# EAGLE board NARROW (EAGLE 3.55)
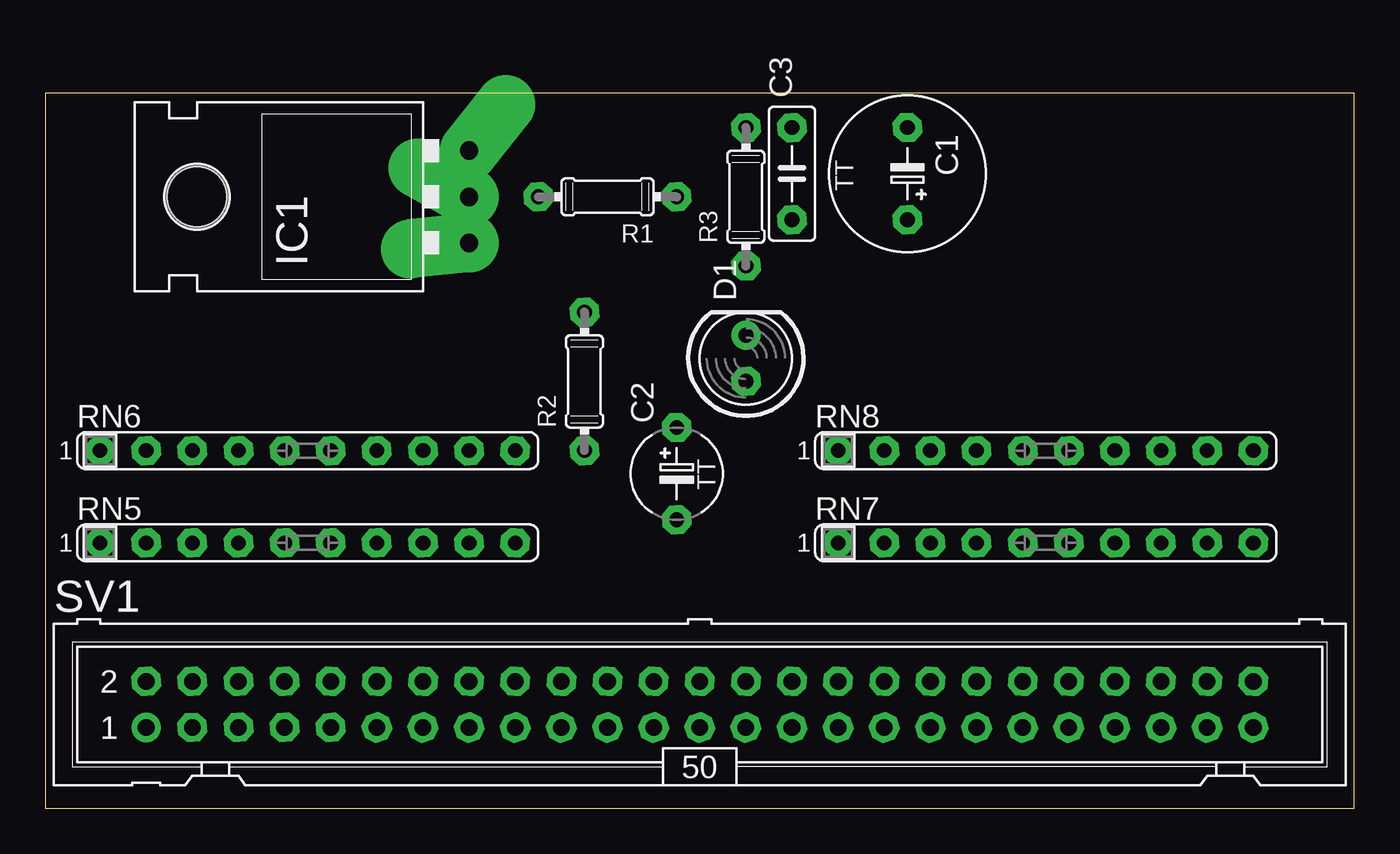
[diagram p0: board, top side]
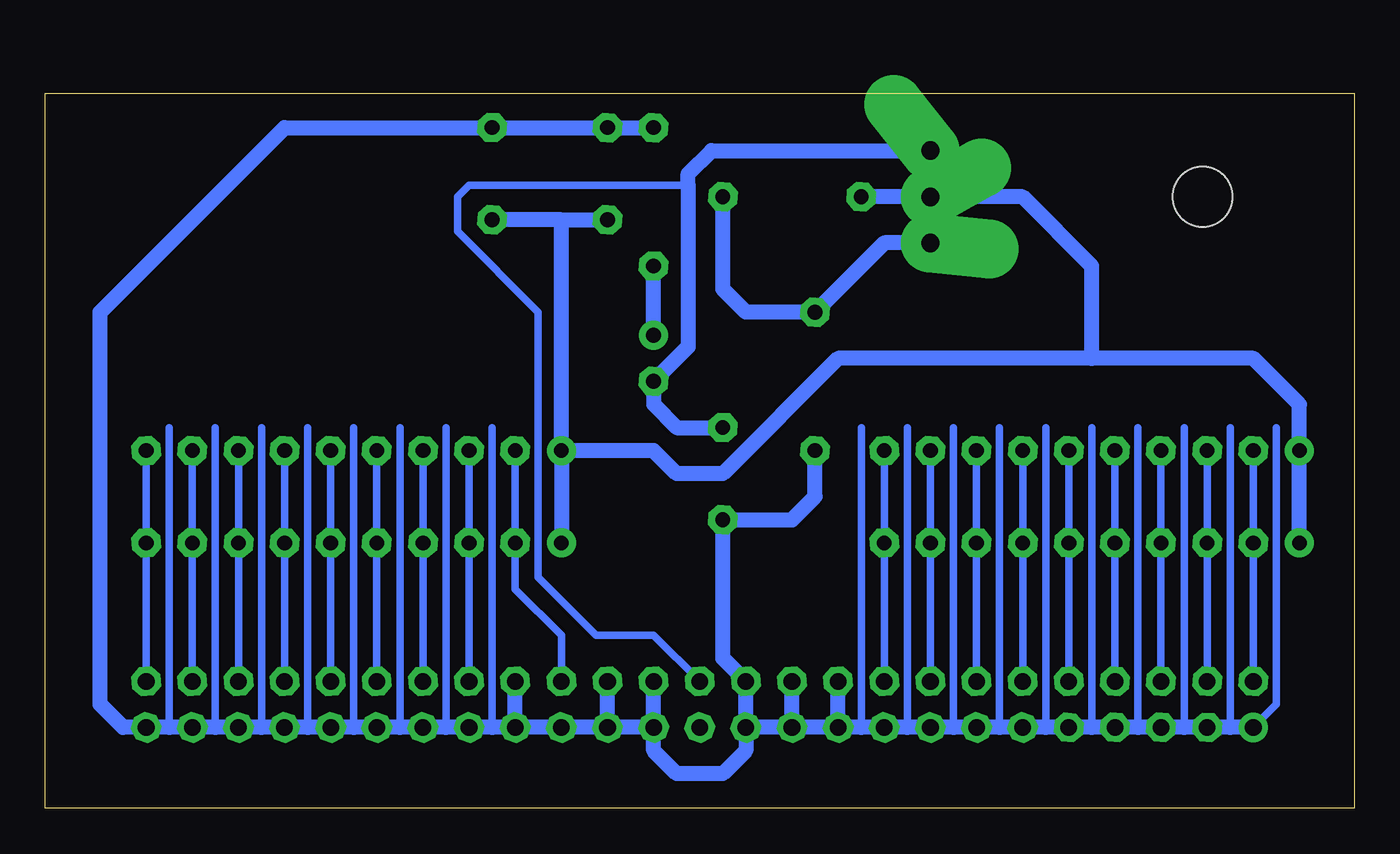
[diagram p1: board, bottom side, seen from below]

Size 72.06 x 39.36 mm. Coordinates in mm from the lower left corner, seen from the top.
Outline: 0,0 72.06,0 72.06,39.36 0,39.36 0,0
Copper layers used: Bottom

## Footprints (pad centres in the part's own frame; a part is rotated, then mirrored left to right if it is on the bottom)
P5-80 = drill 0.813 pad 1.6 octagon:  -2.54,0;  2.54,0
P5-50 = drill 0.813 pad 1.6 octagon:  -2.54,0;  2.54,0
B2,5 = drill 0.813 pad 1.6 octagon:  -2.54,0;  2.54,0
D5 = drill 0.813 pad 1.6 octagon:  -1.27,0 | drill 0.813 pad 1.6 round:  1.27,0
7TL = drill 1.016 pad 3.251 offset:  -2.54,-3.81;  0,-3.81;  2.54,-3.81 | hole 3.302: 0,11.176
04/7 = drill 0.813 pad 1.6 octagon:  -3.81,0;  3.81,0
L10 = drill 0.813 pad 1.6 round:  -11.43,0 | drill 0.813 pad 1.6 octagon:  -8.89,0;  -6.35,0;  -3.81,0;  -1.27,0;  1.27,0;  3.81,0;  6.35,0;  8.89,0;  11.43,0
50 = drill 0.914 pad 1.6 round:  -30.48,-1.27 | drill 0.914 pad 1.6 octagon:  -30.48,1.27;  -27.94,-1.27;  -27.94,1.27;  -25.4,-1.27;  -25.4,1.27;  -22.86,-1.27;  -22.86,1.27;  -20.32,-1.27;  -20.32,1.27;  -17.78,-1.27;  -17.78,1.27;  -15.24,-1.27;  -15.24,1.27;  -12.7,-1.27;  -12.7,1.27;  -10.16,-1.27;  -10.16,1.27;  -7.62,-1.27;  -7.62,1.27;  -5.08,-1.27;  -5.08,1.27;  -2.54,-1.27;  -2.54,1.27;  0,-1.27;  0,1.27;  2.54,-1.27;  2.54,1.27;  5.08,1.27;  5.08,-1.27;  7.62,-1.27;  7.62,1.27;  10.16,1.27;  10.16,-1.27;  12.7,-1.27;  12.7,1.27;  15.24,1.27;  15.24,-1.27;  17.78,-1.27;  17.78,1.27;  20.32,-1.27;  20.32,1.27;  22.86,-1.27;  22.86,1.27;  25.4,-1.27;  25.4,1.27;  27.94,-1.27;  27.94,1.27;  30.48,-1.27;  30.48,1.27

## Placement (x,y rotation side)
C1  22æF  [P5-80]  47.46,34.92 270 top
C2  4.7æF  [P5-50]  34.76,18.41 90 top
C3  100nF  [B2,5]  41.11,34.92 90 top
D1  LED 5mm  [D5]  38.57,24.76 90 top
IC1  LM317TL  [7TL]  19.52,33.65 90 top
R1  121  [04/7]  30.95,33.65 180 top
R2  154  [04/7]  29.68,23.49 90 top
R3  1k5  [04/7]  38.57,33.65 90 top
RN5  220  [L10]  14.44,14.6 0 top
RN6  220  [L10]  14.44,19.68 0 top
RN7  220  [L10]  55.08,14.6 0 top
RN8  220  [L10]  55.08,19.68 0 top
SV1  HE10-50M  [50]  36.03,5.71 0 top

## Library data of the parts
C1 C2 = CAP-TANT
C3 = CAP
D1 = LED
IC1 = V-REG
R1-R3 = R
RN5-RN8 = R-SIL
SV1 = CON-ML

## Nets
C2: RN5. RN6. SV1.
C4: RN5. RN6. SV1.
C6: RN5. RN6. SV1.
C8: RN5. RN6. SV1.
C10: RN5. RN6. SV1.
C12: RN5. RN6. SV1.
C14: RN5. RN6. SV1.
C16: RN5. RN6. SV1.
C18: RN5. RN6. SV1.
C26: C2. D1. IC1. SV1.
C32: RN7. RN8. SV1.
C36: RN7. RN8. SV1.
C38: RN7. RN8. SV1.
C40: RN7. RN8. SV1.
C42: RN7. RN8. SV1.
C44: RN7. RN8. SV1.
C46: RN7. RN8. SV1.
C48: RN7. RN8. SV1.
C50: RN7. RN8. SV1.
GND: C1. C2. C3. R2. R3. SV1.
N$1: C1. C3. IC1. R1. RN5. RN6. RN7. RN8.
N$2: IC1. R1. R2.
N$4: D1. R3.

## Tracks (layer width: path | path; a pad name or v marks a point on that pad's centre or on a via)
C2
  Bottom 0.406: 5.55,6.98 5.55,14.6 5.55,19.68
C4
  Bottom 0.406: 8.09,19.68 8.09,14.6 8.09,6.98
C6
  Bottom 0.406: 10.63,19.68 10.63,14.6 10.63,6.98
C8
  Bottom 0.406: 13.17,19.68 13.17,14.6 13.17,6.98
C10
  Bottom 0.406: 15.71,6.98 15.71,14.6 15.71,19.68
C12
  Bottom 0.406: 18.25,19.68 18.25,14.6 18.25,6.98
C14
  Bottom 0.406: 20.79,6.98 20.79,14.6 20.79,19.68
C16
  Bottom 0.406: 23.33,19.68 23.33,14.6 23.33,6.98
C18
  Bottom 0.406: 25.87,6.98 RN5. RN6.
C26
  Bottom 0.406: 36.67,34.28 48.73,34.28 49.36,33.65 49.36,31.74 44.92,27.3 44.92,12.7 41.75,9.52 38.57,9.52 36.03,6.98
  Bottom 0.813: C2. 37.3,20.95 38.57,22.22 38.57,23.49 36.67,25.39 36.67,34.28 36.67,34.92 35.39,36.19 IC1.
C32
  Bottom 0.406: 46.19,19.68 46.19,14.6 46.19,12.06 43.65,9.52 43.65,6.98
C36
  Bottom 0.406: 48.73,19.68 48.73,14.6 48.73,6.98
C38
  Bottom 0.406: 51.27,6.98 51.27,14.6 51.27,19.68
C40
  Bottom 0.406: 53.81,19.68 53.81,14.6 53.81,6.98
C42
  Bottom 0.406: 56.35,6.98 56.35,14.6 56.35,19.68
C44
  Bottom 0.406: 58.89,19.68 58.89,14.6 58.89,6.98
C46
  Bottom 0.406: 61.43,6.98 61.43,14.6 61.43,19.68
C48
  Bottom 0.406: 63.97,6.98 63.97,14.6 63.97,19.68
C50
  Bottom 0.406: RN8. RN7. SV1.
GND
  Bottom 0.406: 6.82,4.44 6.82,20.95 | 65.24,4.44 65.24,20.95 | 62.7,4.44 62.7,20.95 | 60.16,4.44 60.16,20.95 | 57.62,4.44 57.62,20.95 | 55.08,4.44 55.08,20.95 | 52.54,4.44 52.54,20.95 | 50,4.44 50,20.95 | 47.46,4.44 47.46,20.95 | 24.6,4.44 24.6,20.95 | 22.06,4.44 22.06,20.95 | 19.52,4.44 19.52,20.95 | 16.98,4.44 16.98,20.95 | 14.44,4.44 14.44,20.95 | 11.9,4.44 11.9,20.95 | 9.36,4.44 9.36,20.95 | 5.55,4.44 4.28,5.71 4.28,20.95 | 27.14,4.44 27.14,20.95
  Bottom 0.813: 46.19,4.44 47.46,4.44 48.73,4.44 50,4.44 51.27,4.44 52.54,4.44 53.81,4.44 55.08,4.44 56.35,4.44 57.62,4.44 58.89,4.44 60.16,4.44 61.43,4.44 62.7,4.44 63.97,4.44 65.24,4.44 66.51,4.44 67.78,4.44 69.05,5.71 69.05,27.3 58.89,37.46 47.46,37.46 C3. R3. | 46.19,4.44 43.65,4.44 41.11,4.44 | 38.57,4.44 41.11,4.44 | 38.57,4.44 38.57,6.98 | 41.11,4.44 41.11,6.98 | 46.19,4.44 46.19,6.98 | 30.95,4.44 33.49,4.44 | 28.41,4.44 30.95,4.44 | 28.41,4.44 27.14,4.44 25.87,4.44 24.6,4.44 23.33,4.44 22.06,4.44 20.79,4.44 19.52,4.44 18.25,4.44 16.98,4.44 15.71,4.44 14.44,4.44 13.17,4.44 11.9,4.44 10.63,4.44 9.36,4.44 8.09,4.44 6.82,4.44 5.55,4.44 | 28.41,4.44 28.41,6.98 | 30.95,4.44 30.95,6.98 | 33.49,4.44 33.49,6.98 34.76,8.25 34.76,15.87 30.95,15.87 29.68,17.14 29.68,19.68 | 33.49,4.44 33.49,3.17 34.76,1.9 37.3,1.9 38.57,3.17 38.57,4.44
N$1
  Bottom 0.813: 3.01,14.6 3.01,19.68 3.01,22.22 5.55,24.76 14.44,24.76 | 43.65,19.68 43.65,14.6 | 43.65,32.38 41.11,32.38 | 43.65,32.38 C1. | R1. 23.33,33.65 18.25,33.65 14.44,29.84 14.44,24.76 | 43.65,19.68 43.65,32.38 | 14.44,24.76 28.41,24.76 34.76,18.41 37.3,18.41 38.57,19.68 43.65,19.68
N$2
  Bottom 0.813: 34.76,33.65 34.76,28.57 33.49,27.3 R2. 25.87,31.11 23.33,31.11
N$4
  Bottom 0.813: D1. 38.57,29.84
